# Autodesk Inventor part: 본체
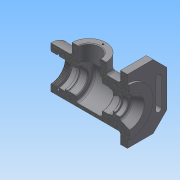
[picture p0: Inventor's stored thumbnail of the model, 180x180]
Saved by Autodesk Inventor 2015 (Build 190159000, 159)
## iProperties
Created: 2017-10
Part Number: 본체
Material: 일반
Document SubType Name: Modeling
Designer: Administrator
Density: 1 g/cm^3
Appearance: 기본값
Mass: 273.32 g
Surface Area: 652.648 cm^2
Volume: 273.32 cm^3
Author: Administrator
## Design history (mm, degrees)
sketch "스케치1"
  geometry: L1 (-56, 0)-(46, 0); L2 (-56, 0)-(-56, 31); L3 (-56, 31)-(46, 31); L4 (46, 31)-(46, 0); 1 further point
  constraints: 8 end point, 2 perpendicular, 1 horizontal, 1 point on line, 1 vertical
  dimensions: "d0" = 102 distance of L1.start L1.end; "d10" = 62 diameter of L3 L1; "d11" = 56 distance of L1.start point (0, 0)
revolve "회전1" sketch "스케치1" stored, may be unused: angle "d12" = 90 deg
sketch "스케치2"
  geometry: L1 (-58, 47)-(58, 47); L2 (58, 47)-(58, -47); L3 (58, -47)-(-58, -47); L4 (-58, -47)-(-58, 47); C1 r 31 at (0, 0) reference; 2 further points
  constraints: 8 end point, 2 midpoint, 2 parallel, 1 horizontal, 1 horizontal alignment, 1 perpendicular, 1 vertical alignment
  dimensions: "d14" = 94 distance of L1.end L2.end; "d15" = 116 distance of L1.start L1.end
extrude "돌출1" join sketch "스케치2" distance "d16" = 10; taper "d17" = 0 deg
sketch "스케치3"
  geometry: C1 r 35 at (0, 0); 1 further point
  constraints: 1 centre point, 1 coincident
  dimensions: "d18" = 70 diameter of C1
extrude "돌출2" join sketch "스케치3" distance "d19" = 3; taper "d20" = 0 deg
sketch "스케치4"
  geometry: C1 r 25 at (0, 0); 1 further point
  constraints: 1 centre point, 1 coincident
  dimensions: "d21" = 50 diameter of C1
extrude "돌출3" join sketch "스케치4" distance "d22" = 47; taper "d23" = 0 deg
sketch "스케치5"
  geometry: L1 (-56, -31)-(-56, 31) reference; L2 (-56, 0)-(59, 0); L3 (59, -35)-(59, 35) reference; L4 (-47, 0)-(-47, 24); L5 (-47, 24)-(-44, 24); L6 (-44, 24)-(-44, 20); L7 (-44, 20)-(-35, 20); L8 (-35, 20)-(-35, 17.5); L9 (-35, 17.5)-(-31.75, 17.5); L10 (-31.75, 17.5)-(-31.75, 18.5); L11 (-31.75, 18.5)-(-30, 18.5); L12 (-30, 18.5)-(-30, 17.5); L13 (-30, 17.5)-(-19, 17.5); L14 (-19, 17.5)-(-19, 26); L15 (-19, 26)-(19, 26); L16 (19, 26)-(19, 17.5); L17 (19, 17.5)-(30, 17.5); L18 (30, 17.5)-(30, 16.5); L19 (30, 16.5)-(35, 16.5); L20 (35, 16.5)-(35, 10); L21 (35, 10)-(37.7, 10); L22 (37.7, 10)-(37.7, 12.5); L23 (37.7, 12.5)-(44.3, 12.5); L24 (45, 12.904)-(45, 16); L25 (45, 16)-(59, 22); L26 (44.3, 12.5)-(45, 12.904); 1 further point
  constraints: 48 end point, 16 perpendicular, 5 vertical, 2 midpoint, 2 point on line
  dimensions: "d26" = 44 diameter of L25.end L2; "d27" = 32 diameter of L24.end L2; "d28" = 14 horizontal distance of L25.end L24.end; "d29" = 52 diameter of L15 L2; "d30" = 35 diameter of L13 L2; "d31" = 35 diameter of L17 L2; "d32" = 33 diameter of L19 L2; "d33" = 48 diameter of L5 L2; "d34" = 40 diameter of L7 L2; "d35" = 35 diameter of L9 L2; "d36" = 12 distance between parallel lines of L1 L6; "d37" = 3 distance of L4.end L5.end; "d38" = 21 distance between parallel lines of L1 L8; "d39" = 26 distance between parallel lines of L1 L12; "d40" = 60 distance between parallel lines of L18 L12; "d41" = 38 distance of L14.end L15.end; "d42" = 5 distance of L18.end L19.end; "d43" = 1.75 distance of L10.end L11.end; "d44" = 37 diameter of L11 L2; "d45" = 25 diameter of L23 L2; "d46" = 20 diameter of L21 L2; "d47" = 2.7 distance of L20.end L21.end; "d49" = 0.7 distance from line of L23.end L24; "d50" = 30 deg angle of L23 L26; "d51" = 11 distance of L12.end L13.end
revolve "회전2" sketch "스케치5" stored, may be unused: angle "d52" = 90 deg
hole "구멍1" diameter "d55" = 32; stored, may be unused: countersink angle "d59" = 90 deg, drill point angle "d61" = 118 deg; dims "d53" = 10, "d54" = 10, "d56" = 6, "d57" = 4, "d58" = 2, "d60" = 40
hole "구멍2" diameter "d64" = 40.376; stored, may be unused: countersink angle "d68" = 90 deg, drill point angle "d70" = 118 deg; dims "d65" = 11, "d66" = 4, "d67" = 2, "d69" = 11.5, "d73" = 10, "d74" = 10
fillet "모깎기1" dims "d71" = 3
fillet "모깎기2" dims "d72" = 0.3
chamfer "모따기1" distance "d75" = 1; stored, may be unused: second distance "d76" = 2, angle "d77" = 45 deg
chamfer "모따기2" distance "d78" = 20; stored, may be unused: second distance "d79" = 2, angle "d80" = 45 deg
sketch "스케치6"
  geometry: L1 (-50, 20)-(-50, -20); L2 (-42, -20)-(-42, 20); C1 r 35 at (0, 0) reference; A1 r 4 centre (-46, -20) between (-50, -20) and (-42, -20); A2 r 4 centre (-46, 20) between (-42, 20) and (-50, 20)
  constraints: 4 end point, 4 point on circle, 4 tangent, 2 centre point, 1 parallel, 1 vertical
  dimensions: "d81" = 46 horizontal distance of A2.centre C1.centre; "d82" = 40 distance of A1.centre A2.centre; "d83" = 20 vertical distance of C1.centre A1.centre; "d84" = 4 radius of A2
extrude "돌출4" cut sketch "스케치6" stored distance "d85" = 0; taper "d86" = 0 deg
node "작업 평면1"
sketch "스케치7"
  geometry: L1 (-56, -31)-(-56, 31) reference; L2 (25, 47)-(-25, 47) reference; 2 further points
  constraints: 1 other
  dimensions: "d87" = 56 distance from line of point (0, 37) L1; "d88" = 10 distance from line of point (0, 37) L2
feature "엠보싱1" sketch "스케치7" dims "d0" = 102, "d10" = 62, "d11" = 56, "d89" = 0.5, "d90" = 0
fillet "모깎기3" dims "d91" = 3
sketch "스케치8"
  geometry: C1 r 25 at (0, 0) reference; C2 r 17 at (0, 0) reference; A1 r 20.5 centre (0, 0) between (0, 20.5) and (0, -20.5)
  constraints: 2 point on circle, 2 vertical alignment, 1 centre point, 1 coincident
  dimensions: "d92" = 41 diameter of A1
hole "구멍3" sketch "스케치8" at (0, 20.5), (0, -20.5) diameter "d93" = 2.459; stored, may be unused: countersink angle "d97" = 90 deg, drill point angle "d99" = 118 deg; dims "d94" = 6, "d95" = 4, "d96" = 2, "d98" = 8
chamfer "모따기3" distance "d100" = 1; stored, may be unused: second distance "d101" = 2, angle "d102" = 45 deg
fillet "모깎기4" dims "d103" = 3
node "솔리드1"
mirror "대칭1"
